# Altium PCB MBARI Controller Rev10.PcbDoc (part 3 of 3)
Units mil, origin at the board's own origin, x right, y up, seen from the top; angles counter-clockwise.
Board outline 10420.2 x 10420.2 mil, 2 copper layers (Top Layer, Bottom Layer); 284 components, 200 nets, 1050 pads, 245 vias.
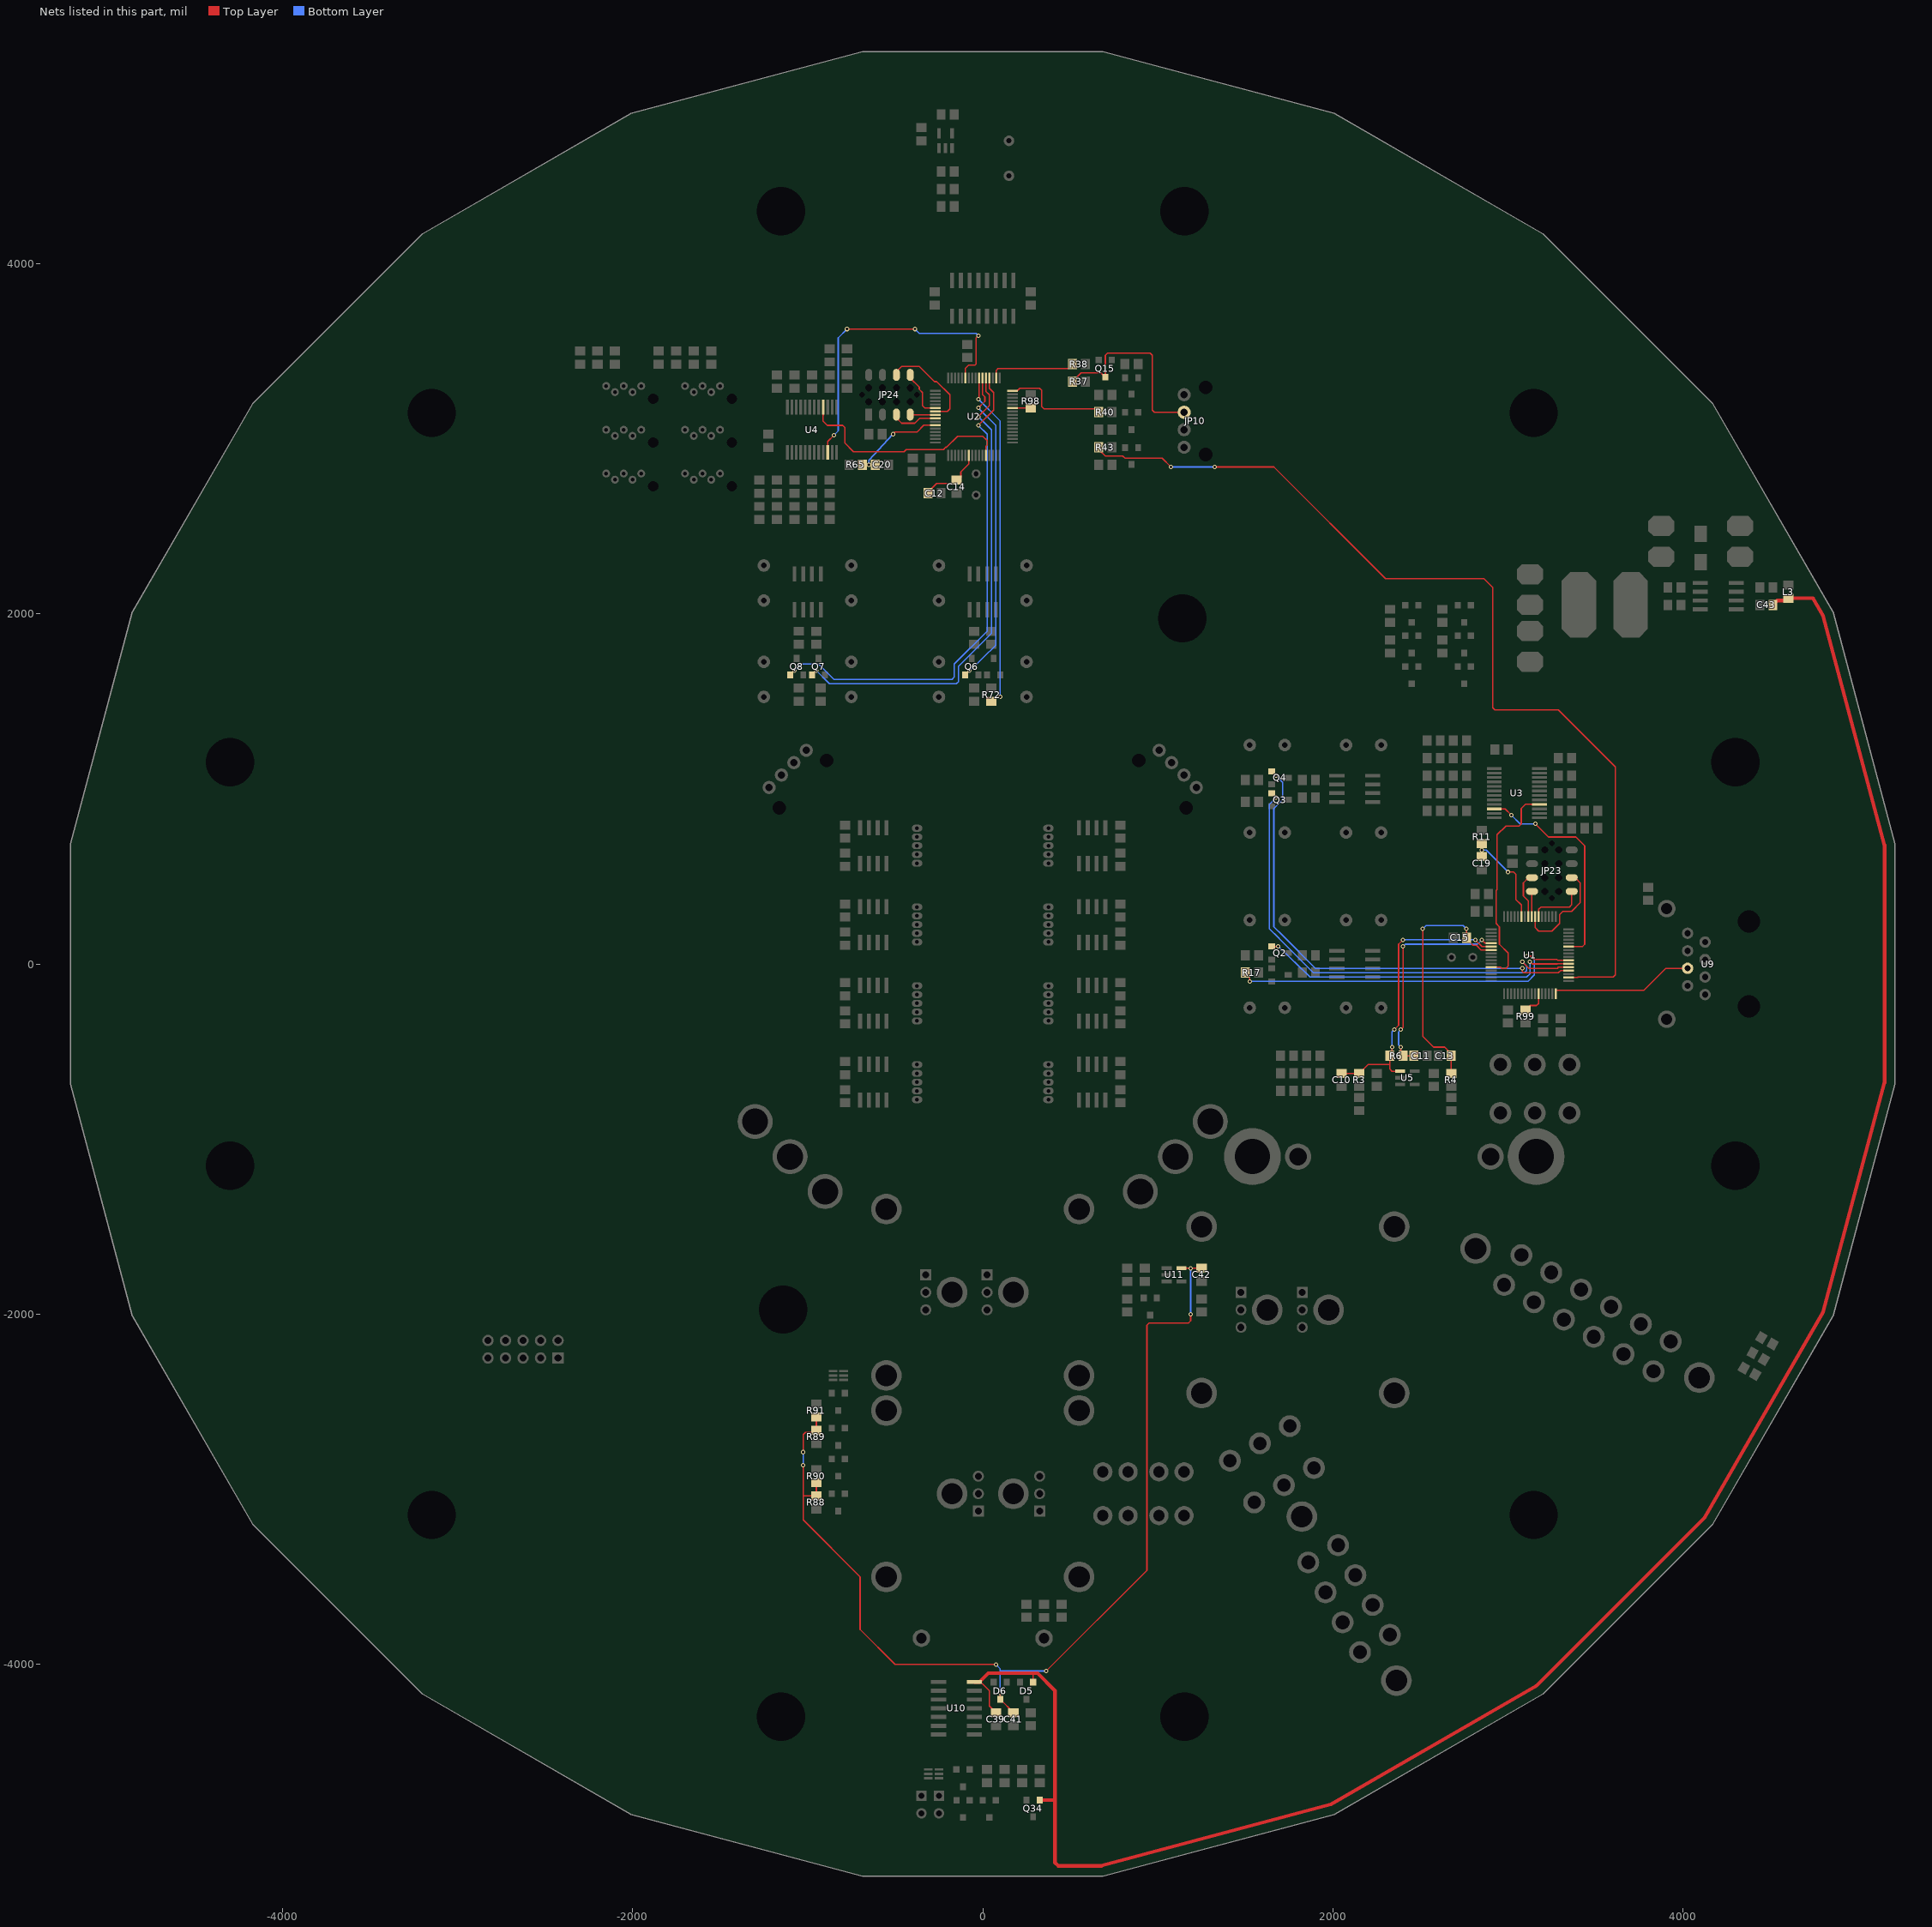
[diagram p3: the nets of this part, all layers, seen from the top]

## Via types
v1: diameter 25, hole 15, Top Layer to Bottom Layer, 205 vias
v2: diameter 40, hole 22, Top Layer to Bottom Layer, 24 vias
v3: diameter 75, hole 50, Top Layer to Bottom Layer, 16 vias

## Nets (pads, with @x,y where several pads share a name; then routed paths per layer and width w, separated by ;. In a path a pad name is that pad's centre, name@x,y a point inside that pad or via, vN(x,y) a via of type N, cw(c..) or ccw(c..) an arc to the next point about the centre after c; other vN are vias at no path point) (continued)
TB0L: Q4.1 U1.36 | length 2740.2
  Top Layer w8: Q4.1@1650,1100 v1(1675,1075) ; v1(3081.25,-25) 3081.25,-43.75 3087.5,-50 3287.5,-50 3300,-37.5 U1.36@3343.75,-37.5
  Bottom Layer w8: v1(1675,1075) 1712.5,1037.5 1712.5,937.5 1662.5,887.5 1662.5,212.5 1712.5,162.5 1900,-25 v1(3081.25,-25)
TB0U: Q8.1 U2.36 | length 2857.3
  Top Layer w8: Q8.1@-1100,1650 v1(-1075,1675) ; v1(-25,3075) 62.5,3162.5 62.5,3262.5 38.58,3286.42 U2.36@38.58,3345.47
  Bottom Layer w8: v1(-1075,1675) -1037.5,1712.5 -937.5,1712.5 -850,1625 -175,1625 -162.5,1637.5 -162.5,1712.5 25,1900 25,3025 v1(-25,3075)
TB1L: Q3.1 U1.37 | length 2721
  Top Layer w8: Q3.1@1650,975 v1(1675,950) ; v1(3081.25,12.5) 3106.25,-12.5 3118.75,-25 3281.55,-25 3287.65,-18.9 U1.37@3345.47,-18.9
  Bottom Layer w8: v1(1675,950) 1637.5,912.5 1637.5,200 1687.5,150 1700,137.5 1887.5,-50 3093.75,-50 3106.25,-37.5 3106.25,-12.5 v1(3081.25,12.5)
TB1U: Q7.1 U2.37 | length 2759.4
  Top Layer w8: Q7.1@-975,1650 v1(-950,1675) ; v1(-25,3125) 37.5,3187.5 37.5,3250 18.9,3268.6 U2.37@18.9,3345.47
  Bottom Layer w8: v1(-950,1675) -875,1600 -150,1600 -137.5,1612.5 -137.5,1700 50,1887.5 50,3050 v1(-25,3125)
TB2L: Q2.1 U1.38 | length 1848.2
  Top Layer w8: Q2.1@1650,99.8 v1(1687.5,100) ; v1(3125,12.5) 3137.5,0 3281.25,0 3282.04,0.79 U1.38@3345.47,0.79
  Bottom Layer w8: v1(1687.5,100) 1868.75,-75 3106.25,-75 3125,-56.25 3125,-12.5 v1(3125,12.5)
TB2U: Q6.1 U2.38 | length 1831.7
  Top Layer w8: Q6.1@-99.8,1650 v1(-75,1675) ; v1(-25,3175) 12.5,3212.5 12.5,3237.5 -0.47,3250.47 ; -0.79,3250.79 -0.79,3275.79 U2.38@-0.79,3345.47
  Bottom Layer w8: v1(-75,1675) 75,1818.75 75,3075 v1(-25,3175)
TB3L: R17.1 U1.39 | length 2088.8
  Top Layer w8: R17.1@1500,-50 1500,-56.25 1525,-81.25 v1(1525,-100) ; v1(3106.25,43.75) 3131.25,43.75 3143.75,31.25 3150,25 3278.44,25 3282.97,20.47 U1.39@3345.47,20.47
  Bottom Layer w8: v1(1525,-100) 3112.5,-100 3150,-62.5 3150,25 3143.75,31.25 3137.5,37.5 3131.25,43.75 v1(3106.25,43.75)
TB3U: R72.1 U2.39 | length 1928.2
  Top Layer w8: v1(-25,3225) -20.47,3229.53 U2.39@-20.47,3345.47 ; R72.1@56.25,1500 81.25,1525 v1(100,1525)
  Bottom Layer w8: v1(-25,3225) 100,3100 v1(100,1525)
TCKL: JP23.3 U1.57 | length 265.5
  Top Layer w8: U1.57@3115.16,270.47 3115.16,359.84 3087.5,387.5 3087.5,462.5 3118.11,493.11 JP23.3@3136.81,493.11
TCKU: JP24.3 U2.57 | length 265.5
  Top Layer w8: JP24.3@-493.11,3136.81 -493.11,3118.11 -462.5,3087.5 -387.5,3087.5 -359.84,3115.16 U2.57@-270.47,3115.16
TDIL: JP23.6 U1.55 | length 600
  Top Layer w8: U1.55@3154.53,270.47 3154.53,207.97 3175,187.5 3250,187.5 3293.75,231.25 3293.75,281.25 3312.5,300 3362.5,300 3412.5,350 3412.5,462.5 3381.89,493.11 JP23.6@3363.19,493.11
TDIU: JP24.6 U2.55 | length 574.4
  Top Layer w8: JP24.6@-493.11,3363.19 -493.11,3381.89 -462.5,3412.5 -362.5,3412.5 -275,3325 -262.5,3325 -187.5,3250 -187.5,3168.75 -201.72,3154.53 U2.55@-270.47,3154.53
TDOL: JP23.5 U1.54 | length 317.4
  Top Layer w8: U1.54@3174.21,270.47 3174.21,311.71 3187.5,325 3350,325 3362.5,337.5 3362.5,413.68 JP23.5@3363.19,414.37
TDOU: JP24.5 U2.54 | length 284.3
  Top Layer w8: JP24.5@-414.37,3363.19 -412.5,3362.5 -412.5,3343.75 -362.5,3293.75 -362.5,3281.25 -343.75,3262.5 -343.75,3187.5 -330.46,3174.21 U2.54@-270.47,3174.21
TMSL: JP23.4 U1.56 | length 144.7
  Top Layer w8: U1.56@3134.84,270.47 3134.84,387.4 3134.84,412.4 JP23.4@3136.81,414.37
TMSU: JP24.4 U2.56 | length 141.9
  Top Layer w8: JP24.4@-412.4,3134.84 -387.4,3134.84 U2.56@-270.47,3134.84
TX0L: U1.32 U9.5 | length 823.2
  Top Layer w8: U1.32@3272.64,-170.47 3272.64,-152.36 3275,-150 3775,-150 3900,-25 U9.5@4025,-25
TX0U: R40.2 U2.32 | length 613.8
  Top Layer w8: U2.32@170.47,3272.64 197.64,3272.64 212.5,3287.5 325,3287.5 337.5,3275 337.5,3181.25 350,3168.75 650,3168.75 662.6,3156.15 R40.2@662.6,3150
TX1L: R43.2 U1.34 | length 5576.9
  Top Layer w8: R43.2@662.6,2950 662.6,2937.4 700,2900 800,2900 812.5,2887.5 1025,2887.5 v1(1075,2837.5) ; v1(1325,2837.5) 1662.5,2837.5 2300,2200 2862.5,2200 2912.5,2150 2912.5,1462.5 2925,1450 3287.5,1450 3612.5,1125 3612.5,-62.5 3600,-75 3400,-75 3397.05,-77.95 U1.34@3345.47,-77.95
  Bottom Layer w8: v1(1075,2837.5) v1(1325,2837.5)
TX1U: R38.2 U2.34 | length 493.9
  Top Layer w8: U2.34@77.95,3345.47 77.95,3390.45 87.5,3400 487.6,3400 R38.2@512.6,3425
TX3V: JP10.2 Q15.3 R37.2 | length 1120.4
  Top Layer w8: R37.2@512.6,3325 562.6,3375 675,3375 699.21,3350.79 Q15.3@700,3350.79 700,3475 712.5,3487.5 956.25,3487.5 968.75,3475 968.75,3162.5 981.25,3150 JP10.2@1150,3150
UP/LOW_L: R99.2 U1.27 | length 144.7
  Top Layer w8: R99.2@3100,-262.5 3125,-237.5 3162.5,-237.5 3174.21,-225.79 U1.27@3174.21,-170.47
UP/LOW_U: R98.2 U2.27 | length 104.9
  Top Layer w8: U2.27@170.47,3174.21 274.21,3174.21 R98.2@275,3175
V_CURRENT_FAST: C10.2 R3.1 R6.2 U1.6 U5.1 | length 1647.7
  Top Layer w8: C10.2@2050,-625.1 R3.1@2150,-625.1 2150,-625 2200,-575 2325.1,-575 ; v1(2337.5,-475) 2337.5,-512.6 R6.2@2325.1,-525 2325.1,-600.1 2337.6,-612.6 U5.1@2382.68,-612.6 ; v1(2350,-375) 2375,-350 2375,112.5 v1(2400,137.5) ; v1(2812.5,137.5) 2850.79,99.21 U1.6@2904.53,99.21
  Bottom Layer w8: v1(2337.5,-475) 2337.5,-387.5 v1(2350,-375) ; v1(2400,137.5) v1(2812.5,137.5)
V_CURRENT_SLOW: C11.1 R6.1 U1.5 | length 1243.5
  Top Layer w8: v1(2387.5,-475) 2387.4,-475.1 2387.4,-525 R6.1@2399.9,-525 C11.1@2462.6,-525 ; v1(2387.5,-375) 2400,-362.5 v1(2400,100) ; v1(2850,137.5) 2868.6,118.9 U1.5@2904.53,118.9
  Bottom Layer w8: v1(2387.5,-475) 2375,-462.5 2375,-387.5 v1(2387.5,-375) ; v1(2400,100) 2412.5,112.5 2825,112.5 v1(2850,137.5)
V_GATE: C41.1 C42.2 D6.3 R88.2 R89.2 R90.2 R91.2 U11.5 | length 5883.4
  Top Layer w8: v1(-1025,-2862.5) -1025,-3175 -700,-3500 -700,-3800 -500,-4000 v1(75,-4000) ; v1(-1025,-2787.5) -1025,-2687.5 -1012.5,-2675 -962.5,-2675 -950.1,-2662.6 R89.2@-950,-2662.6 R91.2@-950,-2587.4 ; -1024.9,-3037.6 R88.2@-950,-3037.6 R90.2@-950,-2962.4 ; v1(100,-4162.5) D6.3@100,-4199.21 175,-4274.21 C41.1@175,-4275 ; v1(362.5,-4037.5) 937.5,-3462.5 937.5,-2062.5 950,-2050 1175,-2050 1187.5,-2037.5 v1(1187.5,-2000) ; U11.5@1134.65,-1737.6 1249.9,-1737.6 C42.2@1250,-1737.5
  Bottom Layer w8: v1(-1025,-2862.5) v1(-1025,-2787.5) ; v1(75,-4000) 100,-4025 v1(100,-4162.5) ; 100,-4037.5 v1(362.5,-4037.5) ; v1(1187.5,-2000) v1(1187.5,-1737.5)
V_ON: C39.2 C43.2 D5.1 L3.1 Q34.1 U10.14 | length 11998.5
  Top Layer w8: U10.14@-18.75,-4100 -12.5,-4100 37.5,-4150 37.5,-4237.5 75,-4275 C39.2@75,-4275.2 ; D5.1@287.4,-4100.79 288.29,-4100.79 288.29,-4050.79 287.5,-4050 ; L3.1@4587.5,2075 L3.1@4600,2087.5 ; L3.1@4600,2075 L3.1@4600,2087.6 ; 4741.43,2087.6 4742.05,2086.52
  Top Layer w20: U10.14@-47.64,-4100 -18.75,-4100 31.25,-4050 312.5,-4050 412.5,-4150 412.5,-5131.25 431.25,-5150 678.01,-5150 1987.83,-4799.04 3162.17,-4121.03 4121.03,-3162.17 4799.04,-1987.83 5150,-678.01 5150,678.01 4799.04,1987.83 4742.05,2086.52 ; Q34.1@325,-4775 412.5,-4775 ; C43.2@4512.4,2050 4537.5,2075 L3.1@4587.5,2075 ; L3.1@4600,2087.6 4741.43,2087.6
VCELL-L: C19.2 R11.2 U1.59 | length 581.2
  Top Layer w8: C19.2@2850,612.4 R11.2@2850,687.6 ; v1(3000,525) 3031.25,525 3043.75,512.5 3043.75,368.75 3075.79,336.71 U1.59@3075.79,270.47
  Bottom Layer w8: v1(2850,650) 2875,650 v1(3000,525)
VCELL-U: C20.2 R65.2 U2.59 | length 566.9
  Top Layer w8: R65.2@-687.7,2850 C20.2@-612.3,2850 ; v1(-512.5,3025) -500,3037.5 -375,3037.5 -336.71,3075.79 U2.59@-270.47,3075.79
  Bottom Layer w8: v1(-650,2850) -650,2875 v1(-512.5,3025)
VREF_L: C13.1 C15.2 R4.1 U1.7 | length 1418.4
  Top Layer w8: v1(2512.5,200) 2512.5,-412.5 2575,-475 2637.5,-475 2675,-512.5 R4.1@2675,-625.1 ; v1(2762.5,200) 2762.4,199.9 C15.2@2762.4,150 2775,137.5 2781.25,125 2800,106.25 2818.75,106.25 2845.47,79.53 U1.7@2904.53,79.53
  Bottom Layer w8: v1(2512.5,200) 2531.25,218.75 2743.75,218.75 v1(2762.5,200)
VREF_U: C12.1 C14.2 U2.7 | length 375.7
  Top Layer w8: C12.1@-312.4,2687.5 -312.4,2693.85 -262.5,2743.75 -168.65,2743.75 C14.2@-150,2762.4 -137.6,2762.4 -125,2775 -125,2809.06 -79.53,2854.53 U2.7@-79.53,2904.53
WDIL: U1.43 U3.10 | length 1263.6
  Top Layer w8: U3.10@2921.06,885.43 2983.32,885.43 v1(3018.75,850) ; v1(3156.25,800) 3231.25,725 3387.5,725 3437.5,675 3437.5,112.5 3425,100 3346.26,100 U1.43@3345.47,99.21
  Bottom Layer w8: v1(3018.75,850) 3068.75,800 v1(3156.25,800)
WDIU: U2.43 U4.10 | length 1810.3
  Top Layer w8: U4.10@-885.43,2921.06 -885.43,2983.32 v1(-850,3018.75) ; v1(-775,3625) v1(-387.5,3625) ; U2.43@-99.21,3345.47 -99.21,3382.04 -100,3400 -81.25,3418.75 -43.75,3418.75 -37.5,3425 -37.5,3575 v1(-25,3587.5)
  Bottom Layer w8: v1(-850,3018.75) -825,3043.75 -825,3575 v1(-775,3625) ; v1(-387.5,3625) -362.5,3600 -37.5,3600 v1(-25,3587.5)
XAL: U1.12 U3.16 | length 1249.9
  Top Layer w8: U1.12@2904.53,-18.9 2956.1,-18.9 2962.2,-25 2987.5,-25 3000,-12.5 3000,62.5 2950,112.5 2950,206.25 2950,212.04 2931.25,231.25 2931.25,418.75 2937.5,425 2937.5,737.5 2987.5,787.5 3062.5,787.5 3075,800 3075,887.5 3100,912.5 3131.25,912.5 3132.73,911.02 U3.16@3178.94,911.02
XAU: U2.12 U4.16 | length 1272.9
  Top Layer w8: U4.16@-911.02,3178.94 -911.02,3132.73 -912.5,3131.25 -912.5,3100 -887.5,3075 -800,3075 -787.5,3062.5 -787.5,2975 -737.5,2925 -450,2925 -437.5,2937.5 -224.54,2937.5 -212.04,2950 -206.25,2950 -143.75,3012.5 0,3012.5 25,2987.5 25,2962.2 18.9,2956.1 U2.12@18.9,2904.53
pads on no net: C1_1.1 C1_1.2 C1_2.1 C1_2.2 C1_3.1 C1_3.2 C1_4.1 C1_4.2 C1_5.1 C1_5.2 C1_6.1 C1_6.2 C1_7.1 C1_7.2 C1_8.1 C1_8.2 D5.2 D6.2 Designator160.0 Designator161.0 Designator162.0 Designator163.0 Designator164.0 Designator165.0 JP1_1.1 JP1_1.2 JP1_1.3 JP1_1.4 JP1_1.5 JP1_2.1 JP1_2.2 JP1_2.3 JP1_2.4 JP1_2.5 JP1_3.1 JP1_3.2 JP1_3.3 JP1_3.4 JP1_3.5 JP1_4.1 JP1_4.2 JP1_4.3 JP1_4.4 JP1_4.5 JP1_5.1 JP1_5.2 JP1_5.3 JP1_5.4 JP1_5.5 JP1_6.1 JP1_6.2 JP1_6.3 JP1_6.4 JP1_6.5 JP1_7.1 JP1_7.2 JP1_7.3 JP1_7.4 JP1_7.5 JP1_8.1 JP1_8.2 JP1_8.3 JP1_8.4 JP1_8.5 JP9.0 JP10.0 JP14.0 JP15.0 JP16.0 JP17.0 JP18.0 JP19.0 JP20.0 JP21.0 JP22.0 JP23.0 JP23.8 JP24.0 JP24.8 R1_1.1 R1_1.2 R1_2.1 R1_2.2 R1_3.1 R1_3.2 R1_4.1 R1_4.2 R1_5.1 R1_5.2 R1_6.1 R1_6.2 R1_7.1 R1_7.2 R1_8.1 R1_8.2 U1.2 U1.3 U1.4 U1.16 U1.17 U1.18 U1.20 U1.21 U1.22 U1.23 U1.24 U1.25 U1.26 U1.40 U1.41 U1.42 U1.44 U1.45 U1.46 U1.47 U1.48 U1.49 U1.50 U1.51 U1.52 U1_1.1 U1_1.2 U1_1.3 U1_1.4 U1_1.5 U1_1.6 U1_1.7 U1_1.8 U1_2.1 U1_2.2 U1_2.3 U1_2.4 U1_2.5 U1_2.6 U1_2.7 U1_2.8 U1_3.1 U1_3.2 U1_3.3 U1_3.4 U1_3.5 U1_3.6 U1_3.7 U1_3.8 U1_4.1 U1_4.2 U1_4.3 U1_4.4 U1_4.5 U1_4.6 U1_4.7 U1_4.8 U1_5.1 U1_5.2 U1_5.3 U1_5.4 U1_5.5 U1_5.6 U1_5.7 U1_5.8 U1_6.1 U1_6.2 U1_6.3 U1_6.4 U1_6.5 U1_6.6 U1_6.7 U1_6.8 U1_7.1 U1_7.2 U1_7.3 U1_7.4 U1_7.5 U1_7.6 U1_7.7 U1_7.8 U1_8.1 U1_8.2 U1_8.3 U1_8.4 U1_8.5 U1_8.6 U1_8.7 U1_8.8 U2.2 U2.3 U2.4 U2.5 U2.6 U2.16 U2.17 U2.18 U2.19 U2.21 U2.22 U2.23 U2.24 U2.25 U2.26 U2.28 U2.29 U2.30 U2.31 U2.40 U2.41 U2.48 U2.52 U2.60 U2.61 U3.17 U3.21 U3.24 U4.17 U4.21 U4.24 U8.7 U8.9 U9.0 U9.7 U10.1 U10.2 U10.3 U10.6 U10.7 U10.8 U10.10 U10.11 U10.12 U10.13
copper on no net: | length 19632.7
  Top Layer w20: -785,-792.4 -702.4,-792.4 -700,-790 -700,-777.36 ; -785,-717.6 -775,-715 -765,-705 -735,-705 -695,-705 -665,-675 -480,-675 -430,-625 -375,-625 ; -785,-632.4 -747.6,-632.4 v2(-735,-645) ; -785,-557.6 -702.4,-557.6 -700,-560 -700,-572.64 ; -785,-342.4 -702.4,-342.4 -700,-340 -700,-327.36 ; -785,-267.6 -775,-265 -765,-255 -735,-255 -695,-255 -665,-225 -480,-225 -430,-175 -375,-175 ; -785,-182.4 -747.6,-182.4 v2(-735,-195) ; -785,-107.6 -702.4,-107.6 -700,-110 -700,-122.64 ; -785,107.6 -702.4,107.6 -700,110 -700,122.64 ; -785,182.4 -775,185 -765,195 -735,195 -695,195 -665,225 -480,225 -430,275 -375,275 ; -785,267.6 -747.6,267.6 v2(-735,255) ; -785,342.4 -702.4,342.4 -700,340 -700,327.36 ; -785,557.6 -702.4,557.6 -700,560 -700,572.64 ; -785,632.4 -775,635 -765,645 -735,645 -695,645 -665,675 -480,675 -430,725 -375,725 ; -785,717.6 -747.6,717.6 v2(-735,705) ; -785,792.4 -702.4,792.4 -700,790 -700,777.36 ; -650,-777.36 -650,-725 -635,-710 -470,-710 -435,-675 -375,-675 ; -650,-572.64 -650,-625 -635,-640 -490,-640 -450,-600 -450,-555 -430,-535 -340,-535 -325,-550 -325,-745 -355,-775 -375,-775 ; -650,-327.36 -650,-275 -635,-260 -470,-260 -435,-225 -375,-225 ; -650,-122.64 -650,-175 -635,-190 -490,-190 -450,-150 -450,-105 -430,-85 -340,-85 -325,-100 -325,-295 -355,-325 -375,-325 ; -650,122.64 -650,175 -635,190 -470,190 -435,225 -375,225 ; -650,327.36 -650,275 -635,260 -490,260 -450,300 -450,345 -430,365 -340,365 -325,350 -325,155 -355,125 -375,125 ; -650,572.64 -650,625 -635,640 -470,640 -435,675 -375,675 ; -650,777.36 -650,725 -635,710 -490,710 -450,750 -450,795 -430,815 -340,815 -325,800 -325,605 -355,575 -375,575 ; -550,-777.36 -540,-775 ; -550,-327.36 -540,-325 ; -550,122.64 -540,125 ; -550,572.64 -540,575 ; -385,-725 -375,-725 ; -385,-275 -375,-275 ; -385,175 -375,175 ; -385,625 -375,625 ; 375,-725 430,-725 480,-675 665,-675 695,-645 735,-645 765,-645 775,-635 785,-632.4 ; 375,-675 435,-675 470,-640 635,-640 650,-625 650,-572.64 ; 375,-625 385,-625 ; 375,-575 355,-575 325,-605 325,-800 340,-815 430,-815 450,-795 450,-750 490,-710 635,-710 650,-725 650,-777.36 ; 375,-275 430,-275 480,-225 665,-225 695,-195 735,-195 765,-195 775,-185 785,-182.4 ; 375,-225 435,-225 470,-190 635,-190 650,-175 650,-122.64 ; 375,-175 385,-175 ; 375,-125 355,-125 325,-155 325,-350 340,-365 430,-365 450,-345 450,-300 490,-260 635,-260 650,-275 650,-327.36 ; 375,175 430,175 480,225 665,225 695,255 735,255 765,255 775,265 785,267.6 ; 375,225 435,225 470,260 635,260 650,275 650,327.36 ; 375,275 385,275 ; 375,325 355,325 325,295 325,100 340,85 430,85 450,105 450,150 490,190 635,190 650,175 650,122.64 ; 375,625 430,625 480,675 665,675 695,705 735,705 765,705 775,715 785,717.6 ; 375,675 435,675 470,710 635,710 650,725 650,777.36 ; 375,725 385,725 ; 375,775 355,775 325,745 325,550 340,535 430,535 450,555 450,600 490,640 635,640 650,625 650,572.64 ; 540,-575 550,-572.64 ; 540,-125 550,-122.64 ; 540,325 550,327.36 ; 540,775 550,777.36 ; 700,-777.36 700,-790 702.4,-792.4 785,-792.4 ; 700,-572.64 700,-560 702.4,-557.6 785,-557.6 ; 700,-327.36 700,-340 702.4,-342.4 785,-342.4 ; 700,-122.64 700,-110 702.4,-107.6 785,-107.6 ; 700,122.64 700,110 702.4,107.6 785,107.6 ; 700,327.36 700,340 702.4,342.4 785,342.4 ; 700,572.64 700,560 702.4,557.6 785,557.6 ; 700,777.36 700,790 702.4,792.4 785,792.4 ; v2(735,-705) 747.6,-717.6 785,-717.6 ; v2(735,-255) 747.6,-267.6 785,-267.6 ; v2(735,195) 747.6,182.4 785,182.4 ; v2(735,645) 747.6,632.4 785,632.4
  Top Layer w25: -5043.75,-195 -3803.75,-195 -3803.75,185 -5043.75,185
  Top Layer w40: -540,-775 v2(-475,-775) -425,-725 -385,-725 ; -540,-325 v2(-475,-325) -425,-275 -385,-275 ; -540,125 v2(-475,125) -425,175 -385,175 ; -540,575 v2(-475,575) -425,625 -385,625 ; 385,-625 425,-625 v2(475,-575) 540,-575 ; 385,-175 425,-175 v2(475,-125) 540,-125 ; 385,275 425,275 v2(475,325) 540,325 ; 385,725 425,725 v2(475,775) 540,775
  Bottom Layer w20: v2(-735,-557.6) v2@-722.4,-555 ; v2(-735,-107.6) v2@-722.4,-105 ; v2(-735,342.4) v2@-722.4,345 ; v2(-735,792.4) v2@-722.4,795 ; -445,-725 -322.5,-725 ; -445,-275 -322.5,-275 ; -445,175 -322.5,175 ; -445,625 -322.5,625 ; 322.5,-625 445,-625 ; 322.5,-175 445,-175 ; 322.5,275 445,275 ; 322.5,725 445,725 ; v2@722.4,-795 v2(735,-792.4) ; v2@722.4,-345 v2(735,-342.4) ; v2@722.4,105 v2(735,107.6) ; v2@722.4,555 v2(735,557.6)

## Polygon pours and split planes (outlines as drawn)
BAT- on Top Layer (hatched 45Degree grid 20 track 25, remove dead copper): 650,-1300 900,-1550 1000,-1550 1150,-1400 1650,-1400 1800,-1250 1800,-950 1750,-900 1650,-900 1498.41,-748.41 1498.41,-450 1600,-350 1600,-225 1550.2,-175 1200.2,-175 1200.2,-650 1200,-650 650,-1200
PWR+ on Top Layer (hatched 45Degree grid 20 track 25, remove dead copper): 945.38,-2837.45 1670.38,-4093.19 2168.35,-3805.69 1443.35,-2549.95 945.38,-2837.45
PWR+ on Top Layer (hatched 45Degree grid 20 track 25, remove dead copper): 1987.5,-2200 1850,-2062.5 937.5,-2062.5 937.5,-3237.5 987.5,-3287.5 1212.5,-3287.5 1987.5,-2512.5
PWR- on Top Layer (hatched 45Degree grid 20 track 25, remove dead copper): 2800,-525 2850,-475 3600,-475 3650,-525 3650,-1887.5 3237.5,-1887.5 3237.5,-1506.74 3225,-1494.46 2900,-1310.22 2900,-1113.7 2800,-1015.43
PWR- on Top Layer (hatched 45Degree grid 20 track 25): 3057.78,-3079.69 3446.69,-2690.78 3093.14,-2337.23 2704.23,-2726.14
PWR- on Top Layer (hatched 45Degree grid 20 track 25): 3057.78,-3079.69 2668.87,-3468.6 2315.32,-3115.04 2704.23,-2726.14
PWRISO+ on Top Layer (hatched 45Degree grid 20 track 25): 2031.36,-2200 2750,-2200 2750,-1287.5 1820.72,-1287.5 1672.04,-1437.5 1399.45,-1437.5 1337.5,-1500 1337.5,-2150 1387.5,-2200
PWR+ on Top Layer (hatched 45Degree grid 20 track 25, remove dead copper): 1444.22,-2549.45 1984.62,-2237.45 2382,-2925.74 1819.08,-3250.74 1421.7,-2562.45
PWR- on Top Layer (hatched 45Degree grid 20 track 25, remove dead copper): 3183.86,-1145.38 3486.97,-1320.38 3724.89,-2208.3 3449.89,-2684.62 3006.05,-2428.37 3262.3,-1984.53 3081.37,-1322.91 3183.86,-1145.38
PWR- on Top Layer (hatched 45Degree grid 20 track 25, remove dead copper): 2382,-2925.74 2978.37,-3958.68 2480.4,-4246.18 1884.03,-3213.24 2382,-2925.74
PWRISO+ on Top Layer (hatched 45Degree grid 20 track 25, remove dead copper): 2584.53,-2185 2962.75,-2403.37 3212.75,-1970.35 3069.24,-1468.92 2744.48,-1281.42 2313.23,-2028.37
NetQ9_5 on Top Layer (hatched 45Degree grid 20 track 25, remove dead copper): 2312.5,-25 2312.5,-262.5 2287.5,-287.5 2262.5,-287.5 2237.5,-262.5 2237.5,-25
NetQ10_5 on Top Layer (hatched 45Degree grid 20 track 25, remove dead copper): 2312.5,975 2312.5,737.5 2287.5,712.5 2262.5,712.5 2237.5,737.5 2237.5,975
NetQ11_5 on Top Layer (hatched 45Degree grid 20 track 25, remove dead copper): 25,2312.5 262.5,2312.5 287.5,2287.5 287.5,2262.5 262.5,2237.5 25,2237.5
NetQ12_5 on Top Layer (hatched 45Degree grid 20 track 25, remove dead copper): -975,2312.5 -737.5,2312.5 -712.5,2287.5 -712.5,2262.5 -737.5,2237.5 -975,2237.5
NetQ9_7 on Top Layer (hatched 45Degree grid 20 track 25, remove dead copper): 2237.5,25 2237.5,262.5 2262.5,287.5 2287.5,287.5 2312.5,262.5 2312.5,25
NetQ10_7 on Top Layer (hatched 45Degree grid 20 track 25, remove dead copper): 2237.5,1025 2237.5,1262.5 2262.5,1287.5 2287.5,1287.5 2312.5,1262.5 2312.5,1025
NetQ11_7 on Top Layer (hatched 45Degree grid 20 track 25, remove dead copper): -25,2237.5 -262.5,2237.5 -287.5,2262.5 -287.5,2287.5 -262.5,2312.5 -25,2312.5
NetQ12_7 on Top Layer (hatched 45Degree grid 20 track 25, remove dead copper): -1025,2237.5 -1262.5,2237.5 -1287.5,2262.5 -1287.5,2287.5 -1262.5,2312.5 -1025,2312.5
BAT+ on Top Layer (hatched 45Degree grid 20 track 25, remove dead copper): -1200,-650 -1400,-650 -1550.5,-802.01 -1550.5,-1299.5 -800,-2050 425,-2050 500,-1975 500,-1231.25 -575,-1230.75 -1150,-650
PWR- on Top Layer (hatched 90Degree grid 5 track 10): -5053.75,-195 -4513.75,-195 -4513.75,185 -5053.75,185
no net on Bottom Layer (hatched 90Degree grid 20 track 25, remove dead copper): 845,-500 275,-500 275,-740 845,-740
no net on Bottom Layer (hatched 90Degree grid 20 track 25): 845,-765 845,-850 275,-850 275,-765
no net on Bottom Layer (hatched 90Degree grid 20 track 25, remove dead copper): 845,-50 275,-50 275,-290 845,-290
no net on Bottom Layer (hatched 90Degree grid 20 track 25): 845,-315 845,-400 275,-400 275,-315
no net on Bottom Layer (hatched 90Degree grid 20 track 25, remove dead copper): 845,400 275,400 275,160 845,160
no net on Bottom Layer (hatched 90Degree grid 20 track 25): 845,135 845,50 275,50 275,135
no net on Bottom Layer (hatched 90Degree grid 20 track 25, remove dead copper): 845,850 275,850 275,610 845,610
no net on Bottom Layer (hatched 90Degree grid 20 track 25): 845,585 845,500 275,500 275,585
no net on Bottom Layer (hatched 90Degree grid 20 track 25, remove dead copper): -845,500 -275,500 -275,740 -845,740
no net on Bottom Layer (hatched 90Degree grid 20 track 25): -845,765 -845,850 -275,850 -275,765
no net on Bottom Layer (hatched 90Degree grid 20 track 25, remove dead copper): -845,-850 -275,-850 -275,-610 -845,-610
no net on Bottom Layer (hatched 90Degree grid 20 track 25): -845,-585 -845,-500 -275,-500 -275,-585
no net on Bottom Layer (hatched 90Degree grid 20 track 25, remove dead copper): -845,-400 -275,-400 -275,-160 -845,-160
no net on Bottom Layer (hatched 90Degree grid 20 track 25): -845,-135 -845,-50 -275,-50 -275,-135
no net on Bottom Layer (hatched 90Degree grid 20 track 25, remove dead copper): -845,50 -275,50 -275,290 -845,290
no net on Bottom Layer (hatched 90Degree grid 20 track 25): -845,315 -845,400 -275,400 -275,315
AGNDU on Bottom Layer (hatched 45Degree grid 20 track 25, remove dead copper): -400,4100 -400,4874.6 -375,4900 375,4900 400,4874.6 400,4100
AGNDU on Bottom Layer (hatched 45Degree grid 20 track 25, remove dead copper): -1400,1425 -1375,1400 375,1400 400,1425 400,4100 375,4100 -600,4100 -900,3800 -2100,3800 -2350,3550 -2350,2625 -2325,2600 -1425,2600 -1400,2575
PWR- on Bottom Layer (hatched 45Degree grid 20 track 25): 3800.7,-2810.75 3190.82,-2200.87 2200.87,-3190.82 2810.75,-3800.7
PWR- on Bottom Layer (hatched 45Degree grid 20 track 25, remove dead copper): 3183.86,-1145.38 3616.88,-1395.38 3799.89,-2078.4 3449.89,-2684.62 3006.05,-2428.37 3262.3,-1984.53 3081.37,-1322.91 3183.86,-1145.38
PWR- on Bottom Layer (hatched 45Degree grid 20 track 25, remove dead copper): 4831.68,-1981.28 4084.73,-1550.03 3384.73,-2762.47 4131.68,-3193.72
PWR- on Bottom Layer (hatched 45Degree grid 20 track 25): 4154.25,-3164.3 3544.37,-2554.42 2554.42,-3544.37 3164.3,-4154.25
PWR- on Bottom Layer (hatched 45Degree grid 20 track 25, remove dead copper): 3193.72,-4131.68 2762.47,-3384.73 1550.03,-4084.73 1981.28,-4831.68
PWR- on Bottom Layer (hatched 45Degree grid 20 track 25, remove dead copper): 2015.54,-4817.49 1792.31,-3984.38 440.01,-4346.73 663.24,-5179.84
PWR- on Bottom Layer (hatched 45Degree grid 20 track 25, remove dead copper): 700,-5175 700,-4312.5 -700,-4312.5 -700,-5175
PWR- on Bottom Layer (hatched 45Degree grid 20 track 25): -663.24,-5179.84 -440.01,-4346.73 -1792.31,-3984.38 -2015.54,-4817.49
PWRF+ on Bottom Layer (hatched 45Degree grid 20 track 25, remove dead copper): 487.5,-2987.5 587.5,-2887.5 587.5,-2787.5 675,-2700 825,-2700 900,-2775 900,-3237.5 637.5,-3500 -325,-3500 -400,-3425 -400,-3062.5 -325,-2987.5 437.5,-2987.5
NetQ23_1 on Bottom Layer (hatched 45Degree grid 20 track 25, remove dead copper): -500,-2485.71 -500,-2450 550,-2450 550,-2557.14 550,-2875 475,-2950 -325,-2950 -500,-2775
PWR+ on Bottom Layer (hatched 45Degree grid 20 track 25, remove dead copper): 1444.22,-2549.45 1984.62,-2237.45 2382,-2925.74 1819.08,-3250.74 1421.7,-2562.45
PWR+ on Bottom Layer (hatched 45Degree grid 20 track 25, remove dead copper): 1987.5,-2200 1850,-2062.5 937.5,-2062.5 937.5,-3237.5 987.5,-3287.5 1212.5,-3287.5 1987.5,-2512.5
PWR- on Bottom Layer (hatched 45Degree grid 20 track 25, remove dead copper): 2382,-2925.74 2978.37,-3958.68 2480.4,-4246.18 1884.03,-3213.24 2382,-2925.74
PWR- on Bottom Layer (hatched 45Degree grid 20 track 25, remove dead copper): 3057.78,-3079.69 2668.87,-3468.6 2315.32,-3115.04 2704.23,-2726.14
PWRISO+ on Bottom Layer (hatched 45Degree grid 20 track 25, remove dead copper): 1857.89,-2025 2031.36,-2200 2750,-2200 2750,-1287.5 1820.72,-1287.5 1672.04,-1437.5 1399.45,-1437.5 1337.5,-1500 1337.5,-1975 1387.06,-2025
PWRISO+ on Bottom Layer (hatched 45Degree grid 20 track 25, remove dead copper): 2584.53,-2185 2962.75,-2403.37 3212.75,-1970.35 3069.24,-1468.92 2744.48,-1281.42 2313.23,-2028.37
BAT+ on Bottom Layer (hatched 45Degree grid 20 track 25, remove dead copper): -1200,-650 -1400,-650 -1550,-800 -1550,-1300 -937.5,-1912.5 225,-1912.5 300,-1836.75 300,-1230.75 -575,-1230.75 -1150,-650
NetQ23_1 on Bottom Layer (hatched 45Degree grid 20 track 25, remove dead copper): 500,-2414.29 500,-2450 -550,-2450 -550,-2342.86 -550,-2025 -475,-1950 325,-1950 500,-2125
BAT- on Bottom Layer (hatched 45Degree grid 20 track 25, remove dead copper): 650,-1300 900,-1550 1000,-1550 1150,-1400 1650,-1400 1800,-1250 1800,-950 1750,-900 1650,-900 1498.41,-748.41 1498.41,-450 1600,-350 1600,-225 1550.2,-175 1200.2,-175 1200.2,-650 1200,-650 650,-1200
PWR+ on Bottom Layer (hatched 45Degree grid 20 track 25, remove dead copper): 945.38,-2837.45 1670.38,-4093.19 2168.35,-3805.69 1443.35,-2549.95 945.38,-2837.45
PWR- on Bottom Layer (hatched 45Degree grid 20 track 25, remove dead copper): 2450,-450 2450,2450 2762.5,2762.5 4375,2762.5 4375,-450 2637.5,-450
PWR- on Bottom Layer (hatched 45Degree grid 20 track 25, remove dead copper): 2800,-450 2850,-450 4300,-450 4300,-500 4300,-1887.5 4092.17,-2247.15 3247.8,-1759.65 3379.05,-1532.32 2976.47,-1300 2976.47,-1100 2800,-1000
PWR- on Bottom Layer (hatched 45Degree grid 20 track 25): 5179.84,-663.24 4346.73,-440.01 3984.38,-1792.31 4817.49,-2015.54
PWR- on Bottom Layer (hatched 45Degree grid 20 track 25): 4817.49,2015.54 3984.38,1792.31 4346.73,440.01 5179.84,663.24
PWR- on Bottom Layer (hatched 45Degree grid 20 track 25, remove dead copper): 5175,700 4312.5,700 4312.5,-700 5175,-700
PWR- on Bottom Layer (hatched 45Degree grid 20 track 25, remove dead copper): 2800,-450 2500,-450 2450,-450 2450,-650 2500,-700 2800,-700 2800,-452.69
PWR- on Bottom Layer (hatched 45Degree grid 20 track 25, remove dead copper): 4381.68,2760.71 3634.73,2329.46 4084.73,1550.03 4831.68,1981.28
PWR- on Bottom Layer (hatched 45Degree grid 20 track 25, remove dead copper): -2400,-2200 -2375,-2175 -2375,-2125 -2400,-2100 -2837.5,-2100 -2925,-2187.5 -2925,-4287.5 -2487.5,-4287.5 -2487.5,-2225 -2462.5,-2200
PWR- on Bottom Layer (hatched 45Degree grid 20 track 25): -1981.28,-4831.68 -1550.03,-4084.73 -2491.83,-3540.98 -2923.08,-4287.93

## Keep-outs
Keep-Out Layer:
  circle w25: c4298.37,-1151.74 r175
  circle w25: c3146.63,-3146.63 r175
  circle w25: c1151.74,-4298.37 r175
  circle w25: c-1151.74,-4298.37 r175
  circle w25: c-3146.63,-3146.63 r175
  circle w25: c-4298.37,-1151.74 r175
  circle w25: c-4298.37,1151.74 r175
  circle w25: c-3146.63,3146.63 r175
  circle w25: c-1151.74,4298.37 r175
  circle w25: c1151.74,4298.37 r175
  circle w25: c3146.63,3146.63 r175
  circle w25: c4298.37,1151.74 r175
  circle w12.5: c-1139.39,-1973.48 r168.75
  circle w12.5: c1139.39,1973.48 r168.75
  circle w50: c0,0 r1335

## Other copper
Top Layer:
  region: 625,-735 500,-735 500,-855 625,-855
  region: 625,-490 575,-490 575,-615 625,-615
  region: 835,-490 265,-490 265,-515 835,-515
  region: 835,-835 265,-835 265,-860 835,-860
  region: 860,-490 825,-490 825,-860 860,-860
  region: 625,-285 500,-285 500,-405 625,-405
  region: 625,-40 575,-40 575,-165 625,-165
  region: 835,-40 265,-40 265,-65 835,-65
  region: 835,-385 265,-385 265,-410 835,-410
  region: 860,-40 825,-40 825,-410 860,-410
  region: 625,165 500,165 500,45 625,45
  region: 625,410 575,410 575,285 625,285
  region: 835,410 265,410 265,385 835,385
  region: 835,65 265,65 265,40 835,40
  region: 860,410 825,410 825,40 860,40
  region: 625,615 500,615 500,495 625,495
  region: 625,860 575,860 575,735 625,735
  region: 835,860 265,860 265,835 835,835
  region: 835,515 265,515 265,490 835,490
  region: 860,860 825,860 825,490 860,490
  rectangle: -625,735 -500,855
  rectangle: -625,490 -575,615
  rectangle: -835,490 -265,515
  rectangle: -835,835 -265,860
  rectangle: -860,490 -825,860
  rectangle: -625,-615 -500,-495
  rectangle: -625,-860 -575,-735
  rectangle: -835,-860 -265,-835
  rectangle: -835,-515 -265,-490
  rectangle: -860,-860 -825,-490
  rectangle: -625,-165 -500,-45
  rectangle: -625,-410 -575,-285
  rectangle: -835,-410 -265,-385
  rectangle: -835,-65 -265,-40
  rectangle: -860,-410 -825,-40
  rectangle: -625,285 -500,405
  rectangle: -625,40 -575,165
  rectangle: -835,40 -265,65
  rectangle: -835,385 -265,410
  rectangle: -860,40 -825,410
  text "Copyright" at 115,820 h35 r270
  text "2005" at 45,740 h35 r270
  text "E" at 205,725 h80 r270
  text "P" at -165,675 h80 r90
  text "P" at 165,675 h80 r270
  text "E" at -205,625 h80 r90
  text "2005" at -45,610 h35 r90
  text "Copyright" at -115,530 h35 r90
  text "Copyright" at 115,370 h35 r270
  text "2005" at 45,290 h35 r270
  text "E" at 205,275 h80 r270
  text "P" at -165,225 h80 r90
  text "P" at 165,225 h80 r270
  text "E" at -205,175 h80 r90
  text "2005" at -45,160 h35 r90
  text "Copyright" at -115,80 h35 r90
  text "27P8S Li-Ion" at -4393.75,25 h40
  text "E" at -4893.75,-25 h150
  text "P" at -4783.75,-75 h150
  text "PCB-150 - Rev1.0" at -4463.75,-75 h40
  text "Copyright" at 115,-80 h35 r270
  text "2005" at 45,-160 h35 r270
  text "Technologies" at -5013.75,-165 h40
  text "E" at 205,-175 h80 r270
  text "P" at -165,-225 h80 r90
  text "P" at 165,-225 h80 r270
  text "E" at -205,-275 h80 r90
  text "2005" at -45,-290 h35 r90
  text "Copyright" at -115,-370 h35 r90
  text "Copyright" at 115,-530 h35 r270
  text "2005" at 45,-610 h35 r270
  text "E" at 205,-625 h80 r270
  text "P" at -165,-675 h80 r90
  text "P" at 165,-675 h80 r270
  text "E" at -205,-725 h80 r90
  text "2005" at -45,-740 h35 r90
  text "Copyright" at -115,-820 h35 r90
Bottom Layer:
  text "TempSens" at -60,825 h40 r90
  text "PCB-151" at -190,800 h40 r90
  text "Rev1.0" at -125,780 h40 r90
  text "Rev1.0" at 125,570 h40 r270
  text "PCB-151" at 190,550 h40 r270
  text "TempSens" at 60,525 h40 r270
  text "TempSens" at -60,375 h40 r90
  text "PCB-151" at -190,350 h40 r90
  text "Rev1.0" at -125,330 h40 r90
  text "Rev1.0" at 125,120 h40 r270
  text "PCB-151" at 190,100 h40 r270
  text "TempSens" at 60,75 h40 r270
  text "Copyright 2005" at -4037.5,12.5 h60
  text "TempSens" at -60,-75 h40 r90
  text "Eagle Picher" at -4100,-87.5 h60
  text "PCB-151" at -190,-100 h40 r90
  text "Rev1.0" at -125,-120 h40 r90
  text "Rev1.0" at 125,-330 h40 r270
  text "PCB-151" at 190,-350 h40 r270
  text "TempSens" at 60,-375 h40 r270
  text "TempSens" at -60,-525 h40 r90
  text "PCB-151" at -190,-550 h40 r90
  text "Rev1.0" at -125,-570 h40 r90
  text "Rev1.0" at 125,-780 h40 r270
  text "PCB-151" at 190,-800 h40 r270
  text "TempSens" at 60,-825 h40 r270
Multi-Layer:
  lines w10 net +3DU: -1500,3300 -1487.63,3312.37

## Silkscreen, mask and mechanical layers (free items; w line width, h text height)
Top Overlay:
  drawing of 192 lines, arcs and shapes, not listed
  text "Observe" at 50,4620 h30
  text "Polarity" at 50,4560 h30
  text "27P8S Li-Ion" at -4393.75,25 h40
  text "PCB-150 - Rev1.0" at -4463.75,-75 h40
  text "Technologies" at -5013.75,-165 h40
  text "TAPE" at -450,-1525 h60
  text "TAPE" at 237.5,-1525 h60
  text "TAPE" at 1350,-1625 h60
  text "TAPE" at 2025,-1625 h60
  text "TAPE" at -225,-2225 h60 r180
  text "TAPE" at 462.5,-2225 h60 r180
  text "TAPE" at 1575,-2325 h60 r180
  text "TAPE" at 2250,-2325 h60 r180
  text "TAPE" at -450,-2675 h60
  text "TAPE" at 237.5,-2675 h60
  text "TAPE" at -225,-3375 h60 r180
  text "TAPE" at 462.5,-3375 h60 r180
Board Outline:
  circle w10: c0,0 r1350
  lines w8: -5205.08,-685.26 -5205.08,685.26 -4850.37,2009.09 -4165.1,3196 -3196,4165.1 -2009.09,4850.37 -685.26,5205.09 685.26,5205.09 2009.09,4850.37 3196,4165.1 4165.1,3196 4850.37,2009.09 5205.09,685.26 5205.09,-685.26 4850.37,-2009.09 4165.1,-3196 3196,-4165.1 2009.09,-4850.37 685.26,-5205.08 -685.26,-5205.08 -2009.09,-4850.37 -3196,-4165.1 -4165.1,-3196 -4850.37,-2009.09 -5205.08,-685.26
  lines w10: -875,-875 -225,-875 cw(c-175,-875) -125,-875 -25,-875 -25,-475 -125,-475 cw(c-175,-475) -225,-475 -875,-475 -875,-875 ; -875,-425 -225,-425 cw(c-175,-425) -125,-425 -25,-425 -25,-25 -125,-25 cw(c-175,-25) -225,-25 -875,-25 -875,-425 ; -875,25 -225,25 cw(c-175,25) -125,25 -25,25 -25,425 -125,425 cw(c-175,425) -225,425 -875,425 -875,25 ; -875,475 -225,475 cw(c-175,475) -125,475 -25,475 -25,875 -125,875 cw(c-175,875) -225,875 -875,875 -875,475 ; 25,-875 25,-475 125,-475 ccw(c175,-475) 225,-475 875,-475 875,-875 225,-875 ccw(c175,-875) 125,-875 25,-875 ; 25,-425 25,-25 125,-25 ccw(c175,-25) 225,-25 875,-25 875,-425 225,-425 ccw(c175,-425) 125,-425 25,-425 ; 25,25 25,425 125,425 ccw(c175,425) 225,425 875,425 875,25 225,25 ccw(c175,25) 125,25 25,25 ; 25,475 25,875 125,875 ccw(c175,875) 225,875 875,875 875,475 225,475 ccw(c175,475) 125,475 25,475
Mech Reference:
  circle w10: c0,0 r6000
  lines w8: -3525,-2350 -1725,-2350 -1725,2350 -3525,2350 -3525,-2350
  text "MBARI Comms" at -3512.5,2287.5 h60
  text "Mounting TBD" at -3256.25,6.25 h120
Mechanical Cells:
  circle w10: c0,-4155.4 r708.66
  circle w10: c-3305.13,4307.33 r708.66
  circle w10: c-2077.69,5015.99 r708.66
  circle w10: c-708.66,5382.82 r708.66
  circle w10: c708.66,5382.82 r708.66
  circle w10: c0,4155.4 r708.66
  circle w10: c2077.69,5015.99 r708.66
  circle w10: c3305.13,4307.33 r708.66
  circle w10: c2077.7,3598.68 r708.66
  circle w10: c4307.33,3305.13 r708.66
  circle w10: c5015.99,2077.69 r708.66
  circle w10: c3598.68,2077.7 r708.66
  circle w10: c2185.45,2185.45 r708.66
  circle w10: c799.93,2985.39 r708.66
  circle w10: c0,1815.38 r708.66
  circle w10: c-799.93,2985.39 r708.66
  circle w10: c-2077.7,3598.68 r708.66
  circle w10: c-4307.33,3305.13 r708.66
  circle w10: c-5015.99,2077.69 r708.66
  circle w10: c-3598.68,2077.7 r708.66
  circle w10: c-2185.45,2185.45 r708.66
  circle w10: c-1572.16,907.69 r708.66
  circle w10: c-2985.39,799.68 r708.66
  circle w10: c-5382.82,708.66 r708.66
  circle w10: c-5382.82,-708.66 r708.66
  circle w10: c-4155.4,0 r708.66
  circle w10: c-2985.39,-799.93 r708.66
  circle w10: c-5015.99,-2077.69 r708.66
  circle w10: c-3598.68,-2077.7 r708.66
  circle w10: c-4307.33,-3305.13 r708.66
  circle w10: c-3305.13,-4307.33 r708.66
  circle w10: c-1572.16,-907.69 r708.66
  circle w10: c-2185.45,-2185.45 r708.66
  circle w10: c-2077.7,-3598.68 r708.66
  circle w10: c-2077.69,-5015.99 r708.66
  circle w10: c-708.66,-5382.82 r708.66
  circle w10: c-799.93,-2985.39 r708.66
  circle w10: c708.66,-5382.82 r708.66
  circle w10: c3305.13,-4307.33 r708.66
  circle w10: c2077.69,-5015.99 r708.66
  circle w10: c0,-1815.38 r708.66
  circle w10: c799.93,-2985.39 r708.66
  circle w10: c2077.7,-3598.68 r708.66
  circle w10: c4307.33,-3305.13 r708.66
  circle w10: c5015.99,-2077.69 r708.66
  circle w10: c3598.68,-2077.7 r708.66
  circle w10: c2185.45,-2185.45 r708.66
  circle w10: c2985.39,-799.93 r708.66
  circle w10: c1572.16,-907.69 r708.66
  circle w10: c1572.16,907.69 r708.66
  circle w10: c2985.39,799.93 r708.66
  circle w10: c4155.4,0 r708.66
  circle w10: c5382.82,708.66 r708.66
  circle w10: c5382.82,-708.66 r708.66
  lines w8: -5949,-783 -5949,783 ; -5948.95,-783.39 -5543.64,-2296.03 ; -5948.95,783.39 -5543.64,2296.03 ; -5543.49,-2296.4 -4760.49,-3652.6 ; -5543.49,2296.4 -4760.49,3652.6 ; -4760.24,-3652.91 -3652.91,-4760.24 ; -4760.24,3652.91 -3652.91,4760.24 ; -3652.6,-4760.49 -2296.4,-5543.49 ; -3652.6,4760.49 -2296.4,5543.49 ; -2296.03,-5543.64 -783.39,-5948.95 ; -2296.03,5543.64 -783.39,5948.95 ; -1039.64,831.42 -707.11,565.69 ; -783,-5949 783,-5949 ; -783,5949 783,5949 ; -133.79,866.23 133.79,866.23 ; 329.53,843.45 399.07,1020.98 ; 783.39,-5948.95 2296.03,-5543.64 ; 783.39,5948.95 2296.03,5543.64 ; 2296.4,-5543.49 3652.6,-4760.49 ; 2296.4,5543.49 3652.6,4760.49 ; 3652.91,-4760.24 4760.24,-3652.91 ; 3652.91,4760.24 4760.24,3652.91 ; 4760.49,-3652.6 5543.49,-2296.4 ; 4760.49,3652.6 5543.49,2296.4 ; 5543.64,-2296.03 5948.95,-783.39 ; 5543.64,2296.03 5948.95,783.39 ; 5949,-783 5949,783 ; -1300,-225 -1300,225 -1150,300 -1150,-300 -1300,-225 ; 1150,-300 1300,-225 1300,225 1150,300 1150,-300
  lines w10: -1039.64,831.42 ccw(c0,0) -1240.84,482.09 cw(c-1815.38,0) -1240.84,-482.09 ccw(c0,0) -1037.92,-833.56 cw(c-907.69,-1572.16) -202.92,-1315.65 ccw(c0,0) 202.92,-1315.65 cw(c907.69,-1572.16) 1037.92,-833.56 ccw(c0,0) 1240.84,-482.09 cw(c1815.38,0) 1240.84,482.09 ccw(c0,0) 1037.92,833.56 cw(c907.69,1572.16) 399.07,1020.98 ; -707.11,565.69 ccw(c-636.4,636.4) -565.69,565.69 cw(c0,0) 207.06,772.74 ccw(c232.94,869.33) 329.53,843.45 ; -650.86,1182.74 cw(c-530.33,963.72) -282.47,996.35 ; -282.51,996.65 ccw(c-133.79,1016.23) -114.21,867.51 ; 114.21,867.51 ccw(c133.79,1016.23) 282.51,996.65 ; 282.47,996.35 cw(c530.33,963.72) 650.86,1182.74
